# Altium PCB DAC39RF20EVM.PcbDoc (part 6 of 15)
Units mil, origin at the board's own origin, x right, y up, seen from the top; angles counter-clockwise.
Board outline 6200 x 2716.54 mil, 16 copper layers (Top Layer, L2 GND, L3 PWR, L4 GND, L5 PWR, L6 GND, L7 SIG, L8 GND, L9 GND, L10 SIG, L11 GND, L12 PWR, L13 GND, L14 PWR, L15 GND, Bottom Layer), stack 76.97 mil thick; 766 components, 495 nets, 3414 pads, 2373 vias.
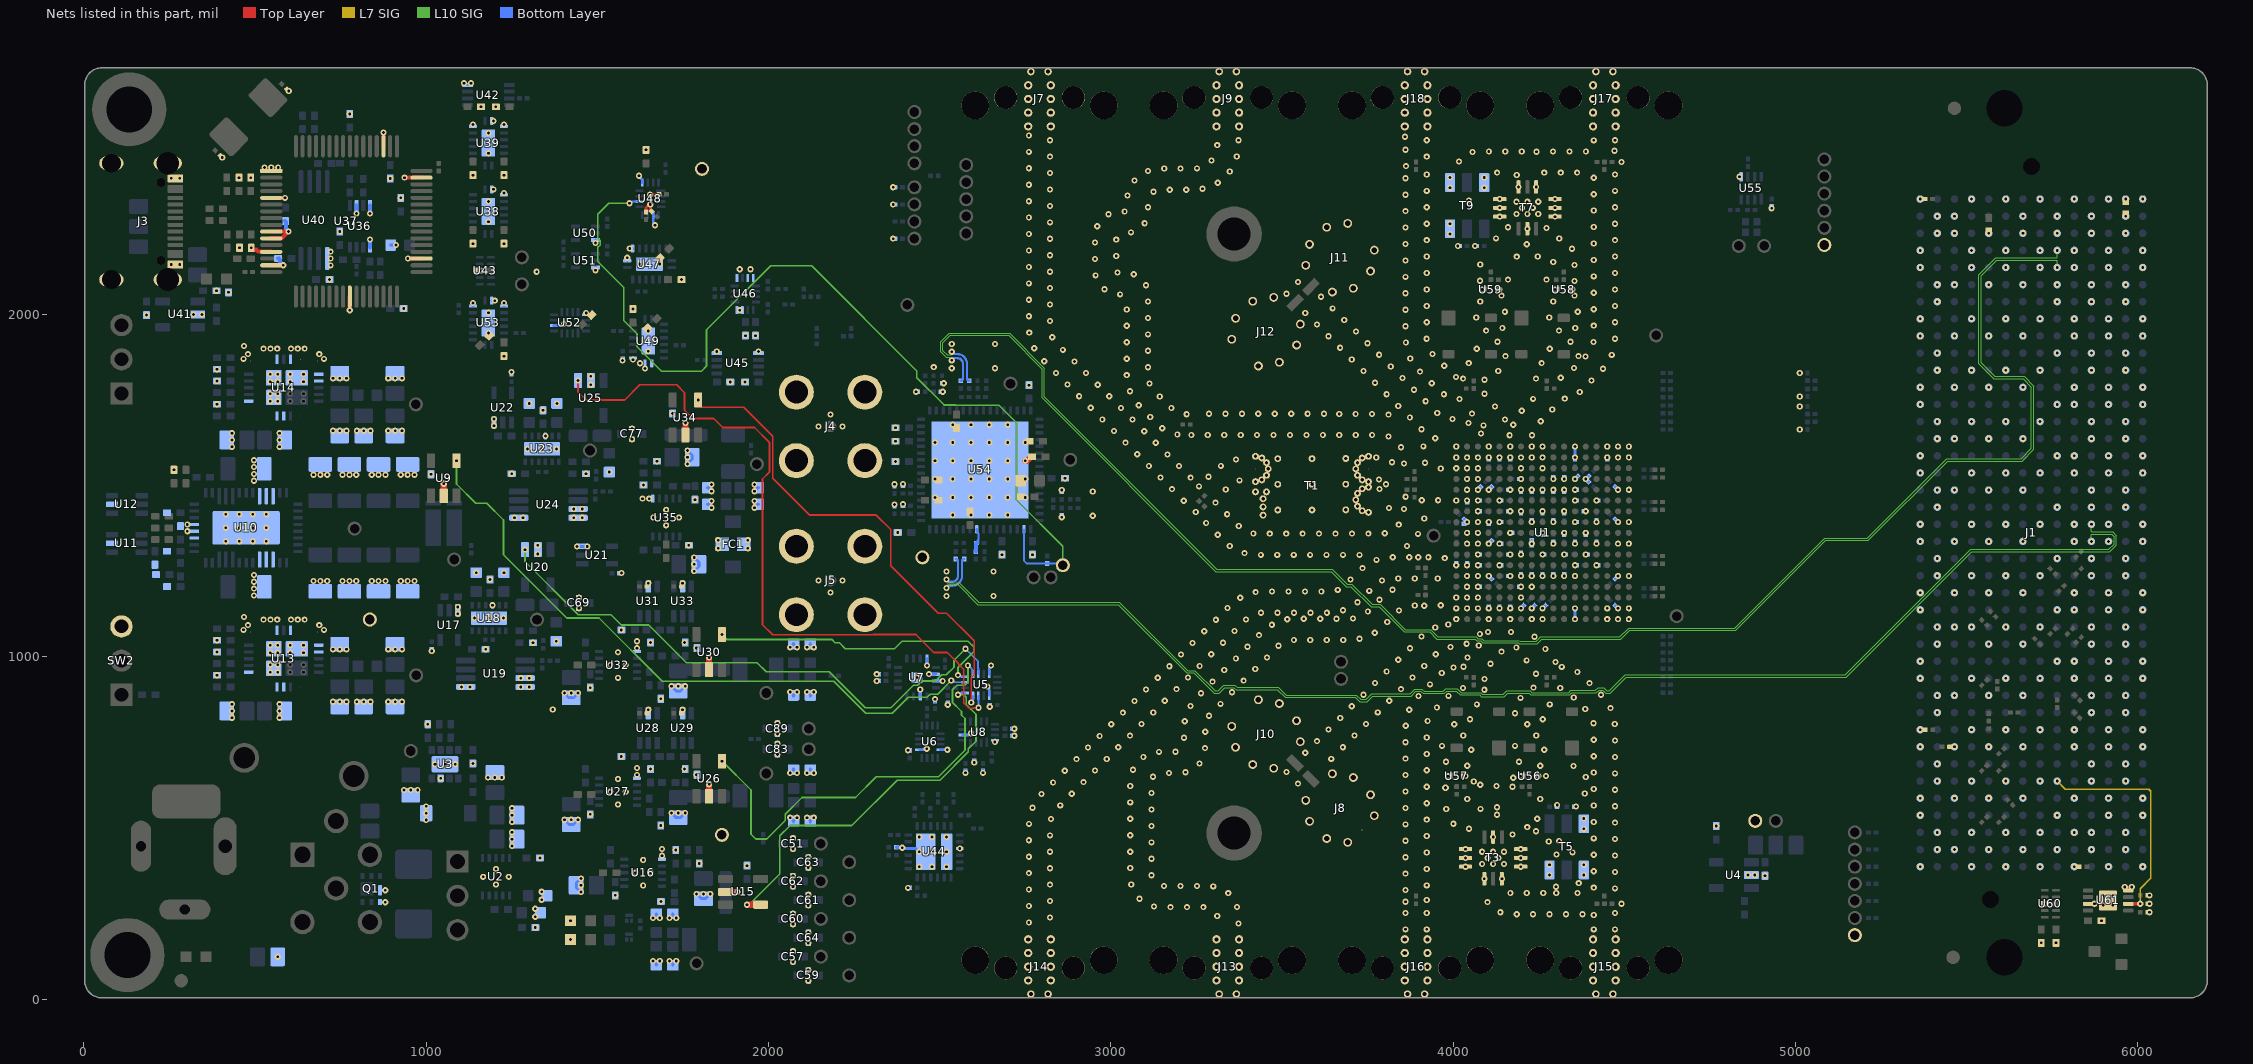
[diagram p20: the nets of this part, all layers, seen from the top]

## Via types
v1: diameter 18, hole 8, Top Layer to Bottom Layer, tented both sides, 2344 vias
v2: diameter 24, hole 12, Top Layer to Bottom Layer, tented both sides, 19 vias
v3: diameter 18, hole 8, Top Layer to Bottom Layer, tented bottom, 9 vias
v4: diameter 20, hole 10, Top Layer to Bottom Layer, tented both sides, 1 vias

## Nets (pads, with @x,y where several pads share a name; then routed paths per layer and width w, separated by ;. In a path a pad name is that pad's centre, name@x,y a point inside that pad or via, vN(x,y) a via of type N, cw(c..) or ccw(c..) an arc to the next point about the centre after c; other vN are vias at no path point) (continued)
GA1_FMC: J1.D35 R196.2 U61.2 | length 662.6
  Top Layer w10: U61.2@5971.65,278.48 v1(6006.65,278.48)
  L7 SIG w5: v1(5764.01,637.07) 5788.05,613.03 6031.97,613.03 6037.59,607.4 6037.59,353.8 6006.65,322.86 v1(6006.65,278.48)
GBTCLK0_FMC_n: C173.1 J1.D5 | length 4914.1
  L10 SIG w3: v1(2535.13,1890.86) 2535.13,1883.59 2533.38,1881.84 2521.81,1881.84 2509.4,1894.25 2509.4,1916.84 2531.07,1938.5 2701.01,1938.5 2798.9,1840.62 2798.9,1756.94 3306.99,1248.85 3643.61,1248.85 3687.39,1205.07 3700.97,1205.07 3759.97,1146.07 3783.69,1146.07 3857.15,1072.61 3931.31,1072.61 3952.24,1051.68 4063.71,1051.68 4068.86,1046.53 4079.9,1046.53 4085.95,1040.48 4189.93,1040.48 4192.39,1038.02 4245.8,1038.02 4258.78,1051 4489.51,1051 4515.38,1076.88 4825.68,1076.88 5088.5,1339.7 5212.86,1339.7 5444.84,1571.69 5661.8,1571.69 5696.01,1605.9 5696.01,1789.97 5667.18,1818.8 5582.28,1818.8 5542.61,1858.47 5542.61,2113.39 5587.78,2158.57 5762.25,2158.57 5764.01,2156.81 v1(5764.01,2137.07)
  Bottom Layer w6.3: v1@2534.74,1890.86 ccw(c2541.36,1890.86) 2541.36,1884.24 2551.25,1884.24 cw(c2551.25,1855.77) 2579.71,1855.77 2579.71,1812.73 ccw(c2586.34,1812.73) C173.1@2586.34,1806.11
GBTCLK0_FMC_p: C172.1 J1.D4 | length 4918.7
  L10 SIG w3: v1(2535.13,1865.81) 2535.13,1873.08 2533.38,1874.84 2518.91,1874.84 2502.4,1891.35 2502.4,1906.43 2502.4,1919.73 2528.17,1945.5 2703.91,1945.5 2805.9,1843.52 2805.9,1759.84 3309.89,1255.85 3646.51,1255.85 3690.29,1212.07 3703.87,1212.07 3762.87,1153.07 3786.59,1153.07 3860.05,1079.61 3934.21,1079.61 3955.14,1058.68 4066.61,1058.68 4072.18,1053.11 4083.22,1053.11 4088.85,1047.48 4192.83,1047.48 4195.29,1045.02 4242.9,1045.02 4255.88,1058 4486.61,1058 4512.48,1083.88 4822.78,1083.88 5085.61,1346.7 5209.96,1346.7 5441.94,1578.69 5658.9,1578.69 5689.01,1608.8 5689.01,1787.07 5664.28,1811.8 5579.38,1811.8 5535.61,1855.57 5535.61,2116.29 5584.88,2165.57 5762.25,2165.57 5764.01,2167.32 v1(5764.01,2187.07)
  Bottom Layer w6.3: v1@2534.74,1865.81 cw(c2541.36,1865.81) 2541.36,1872.44 2551.25,1872.44 cw(c2551.25,1855.77) 2567.91,1855.77 2567.91,1812.73 cw(c2561.29,1812.73) C172.1@2561.29,1806.11
GBTCLK1_FMC_n: C169.1 J1.B21 | length 4002.5
  L10 SIG w3: v1(2520.05,1225.85) 2520.05,1218.58 2521.81,1216.82 2556.88,1216.82 2614.31,1159.39 3025.13,1159.39 3224.63,959.89 3245.64,959.89 3305.22,900.31 3313.2,900.31 3329.82,916.93 3362.38,916.93 3368.53,910.78 3489.01,910.78 3511.54,888.25 3717.14,888.25 3729.53,875.87 3745.76,875.87 3762.01,892.12 3841.61,892.12 3841.67,892.06 3873.97,892.06 3887.79,905.88 3908.74,905.88 3914.66,899.96 3971.17,899.96 3977.67,906.46 4011.71,906.46 4022.69,895.48 4080.07,895.48 4085.26,890.28 4146.22,890.28 4156.54,900.61 4224.49,900.61 4229.62,895.48 4337.03,895.48 4343.3,901.75 4415.19,901.75 4423.03,909.6 4440.18,909.6 4448.89,900.88 4456.26,900.88 4502.9,947.52 5145.47,947.52 5511.8,1313.85 5915.07,1313.85 5930.22,1329 5930.22,1351.18 5922.84,1358.57 5865.77,1358.57 5864.01,1356.81 v1(5864.01,1337.07)
  Bottom Layer w6.3: v1(2520.05,1225.85) ccw(c2526.68,1225.85) 2526.68,1219.22 2536.57,1219.22 ccw(c2536.57,1235.89) 2553.23,1235.89 2553.23,1278.93 ccw(c2546.61,1278.93) C169.1@2546.61,1285.55
GBTCLK1_FMC_p: C168.1 J1.B20 | length 4044.2
  L10 SIG w3: v1(2520.05,1200.8) 2520.05,1208.07 2521.81,1209.82 2553.98,1209.82 2611.41,1152.39 3022.23,1152.39 3221.73,952.89 3242.74,952.89 3302.33,893.31 3316.1,893.31 3332.72,909.93 3359.48,909.93 3365.63,903.78 3486.11,903.78 3508.64,881.25 3714.24,881.25 3726.63,868.87 3748.66,868.87 3764.91,885.12 3838.71,885.12 3838.77,885.06 3876.87,885.06 3890.69,898.88 3905.84,898.88 3911.76,892.96 3974.07,892.96 3980.57,899.46 4008.81,899.46 4019.79,888.48 4077.17,888.48 4082.37,883.28 4149.12,883.28 4159.44,893.61 4221.59,893.61 4226.72,888.48 4339.93,888.48 4346.2,894.75 4418.09,894.75 4425.93,902.6 4437.28,902.6 4445.99,893.88 4459.16,893.88 4505.8,940.52 5148.37,940.52 5514.7,1306.85 5917.97,1306.85 5937.22,1326.1 5937.22,1354.08 5925.74,1365.57 5865.77,1365.57 5864.01,1367.32 v1(5864.01,1387.07)
  Bottom Layer w6.3: v1(2520.05,1200.8) cw(c2526.68,1200.8) 2526.68,1207.42 2536.57,1207.42 ccw(c2536.57,1235.89) 2565.03,1235.89 2565.03,1278.93 cw(c2571.65,1278.93) C168.1@2571.65,1285.55
GND: C2.1 C3.1 C4.1 C5.1 C6.1 C7.1 C8.1 C9.1 C10.1 C11.2 C12.2 C13.2 C14.2 C15.2 C16.2 C17.2 C18.2 C19.1 C20.1 C21.1 C22.1 C23.1 C24.1 C25.1 C26.1 C27.1 C28.1 C29.1 C30.1 C31.1 C32.1 C33.1 C34.1 C35.1 C36.1 C37.1 C38.1 C39.2 C40.1 C41.1 C42.1 C43.1 C44.1 C45.1 C46.1 C47.2 C48.1 C49.1 C50.1 C51.2 C52.1 C53.1 C54.1 C55.1 C56.1 C57.2 C58.1 C59.2 C60.2 C61.2 C62.2 C63.2 C64.2 C65.1 C66.1 C67.1 C69.2 C70.1 C71.1 C72.1 C73.1 C74.1 C75.1 C77.2 C78.1 C79.1 C80.1 C81.1 C82.1 C83.2 C84.1 C85.1 C86.1 C87.1 C88.1 C89.2 C90.1 C91.1 C92.1 C93.1 C94.1 C95.1 C96.1 C97.1 C98.1 C99.1 C100.2 C101.2 C102.2 C103.2 C104.1 C105.1 C106.1 C107.1 C108.1 C109.1 C110.1 C111.1 C112.1 C113.1 C114.1 C115.1 C116.1 C117.1 C118.1 C119.1 C120.1 C121.1 C122.1 C123.1 C124.1 C125.1 C126.1 C127.1 C128.1 C129.1 C130.1 C131.1 C132.1 C133.1 C134.1 C135.1 C136.2 C137.2 C138.2 C139.2 C140.1 C141.2 C142.2 C143.2 C144.2 C145.1 C146.1 C147.2 C148.2 C149.2 C150.2 C151.2 C152.2 C153.2 C154.2 C155.2 C156.2 C157.2 C158.2 C159.2 C161.1 C164.1 C176.1 C177.2 C217.1 C219.1 C226.2 C227.2 C234.2 C235.2 C236.2 C237.2 C238.2 C239.2 C240.2 C241.2 C242.2 C243.2 C244.2 C245.2 C246.2 C247.2 C248.2 C249.2 C250.2 C251.2 C252.2 C253.2 C254.2 C255.2 C256.2 C257.2 C258.2 C259.2 C260.2 C261.2 C262.2 C263.2 C264.2 C265.2 C266.2 C267.2 C268.2 C269.2 C270.2 C271.2 C272.2 C273.2 C274.2 C275.2 C276.2 C277.2 C278.2 C279.2 C280.2 C281.2 C282.2 C283.2 C284.2 C285.2 C286.2 C287.2 C288.2 C289.2 C290.2 C291.2 C292.2 C293.2 C294.2 C295.2 C296.2 C297.2 C298.2 C299.2 C300.2 C301.2 C302.2 C303.2 C304.2 C305.2 C306.2 C307.2 C308.2 C309.2 C310.2 C311.2 C312.2 C313.2 C314.2 C315.1 C316.1 D3.2 D6.2 D7.2 FC1.2 J1.A1 J1.A4 J1.A5 J1.A8 J1.A9 J1.A12 J1.A13 J1.A16 J1.A17 J1.A20 J1.A21 J1.A24 J1.A25 J1.A28 J1.A29 J1.A32 J1.A33 J1.A36 J1.A37 J1.A40 J1.B2 J1.B3 J1.B6 J1.B7 J1.B10 J1.B11 J1.B14 J1.B15 J1.B18 J1.B19 J1.B22 J1.B23 J1.B26 J1.B27 J1.B30 J1.B31 J1.B34 J1.B35 J1.B38 J1.B39 J1.C1 J1.C4 J1.C5 J1.C8 J1.C9 J1.C12 J1.C13 J1.C16 J1.C17 J1.C20 J1.C21 J1.C24 J1.C25 J1.C28 J1.C29 J1.C32 J1.C33 J1.C36 J1.C38 J1.C40 J1.D2 J1.D3 J1.D6 J1.D7 J1.D10 J1.D13 J1.D16 J1.D19 J1.D22 J1.D25 J1.D28 J1.D37 J1.D39 J1.E1 J1.E4 J1.E5 J1.E8 J1.E11 J1.E14 J1.E17 J1.E20 J1.E23 J1.E26 J1.E29 J1.E32 J1.E35 J1.E38 J1.E40 J1.F2 J1.F3 J1.F6 J1.F9 J1.F12 J1.F15 J1.F18 J1.F21 J1.F24 J1.F27 J1.F30 J1.F33 J1.F36 J1.F39 J1.G1 J1.G4 J1.G5 J1.G8 J1.G11 J1.G14 J1.G17 J1.G20 J1.G23 J1.G26 J1.G29 J1.G32 J1.G35 J1.G38 J1.G40 J1.H3 J1.H6 J1.H9 J1.H12 J1.H15 J1.H18 J1.H21 J1.H24 J1.H27 J1.H30 J1.H33 J1.H36 J1.H39 J1.J1 J1.J4 J1.J5 J1.J8 J1.J11 J1.J14 J1.J17 J1.J20 J1.J23 J1.J26 J1.J29 J1.J32 J1.J35 J1.J38 J1.J40 J1.K2 J1.K3 J1.K6 J1.K9 J1.K12 J1.K15 J1.K18 J1.K21 J1.K24 J1.K26 J1.K30 J1.K33 J1.K36 J1.K39 J1.L2 J1.L3 J1.L6 J1.L7 J1.L10 J1.L11 J1.L14 J1.L15 J1.L18 J1.L19 J1.L22 J1.L23 J1.L26 J1.L27 J1.L30 J1.L31 J1.L34 J1.L35 J1.L38 J1.L39 J1.M1 J1.M4 J1.M5 J1.M8 J1.M9 J1.M12 J1.M13 J1.M16 J1.M17 J1.M20 J1.M21 J1.M24 J1.M25 J1.M28 J1.M29 J1.M32 J1.M33 J1.M36 J1.M37 J1.M40 J1.Y1 J1.Y4 J1.Y5 J1.Y8 J1.Y9 J1.Y12 J1.Y13 J1.Y16 J1.Y17 J1.Y20 J1.Y21 J1.Y24 J1.Y25 J1.Y28 J1.Y29 J1.Y32 J1.Y33 J1.Y36 J1.Y37 J1.Y40 J1.Z2 J1.Z3 J1.Z6 J1.Z7 J1.Z10 J1.Z11 J1.Z14 J1.Z15 J1.Z18 J1.Z19 J1.Z22 J1.Z23 J1.Z26 J1.Z27 J1.Z30 J1.Z31 J1.Z34 J1.Z35 J1.Z38 J1.Z39 J3.1 J3.2 J3.3 J3.4 J3.A1 J3.B1 J4.2 J4.3 J4.4 J4.5 J5.2 J5.3 J5.4 J5.5 J7.2 J7.3 J7.4 J8.2 J9.2 J9.3 J9.4 J10.2 J11.2 J12.2 J13.2 J13.3 J13.4 J14.2 J14.3 J14.4 J15.2 J15.3 J15.4 J16.2 J16.3 J16.4 J17.2 J17.3 J17.4 J18.2 J18.3 J18.4 pad.1@942.86,1346.82 pad.1@5001.22,1375.07 PP3.1 PP4.1 PP5.1 PP6.1 PP7.1 PP8.1 PP9.1 Q1.4 Q1.7 R2.1 R3.1 R4.1 R11.1 R13.2 R14.2 R15.2 R25.1 R27.1 R28.1 R30.2 R31.2 R36.1 R37.1 R41.1 R42.1 R48.1 R50.1 R55.1 R56.1 R63.1 R64.1 R73.1 R74.2 R76.1 R81.2 R86.1 R88.1 R94.1 R96.1 R108.1 R110.1 R130.2 R131.2 R142.2 R143.2 R144.2 R148.2 R154.2 R155.2 R156.2 R157.1 R159.1 R160.1 R161.1 R166.1 R167.1 R168.1 R169.1 R170.1 R181.1 R194.1 R195.1 R196.1 R197.1 R198.1 R220.1 R229.1 R230.1 R231.1 R232.1 SW2.2 T1.4 T3.2 T3.4 T3.5 T3.6 T3.7 T3.9 T3.10 T3.11 T3.12 T3.13 T5.3 T5.4 T5.6 T7.2 T7.4 T7.5 T7.6 T7.7 T7.9 T7.10 T7.11 T7.12 T7.13 T9.3 T9.4 T9.6 U1.A1 U1.A2 U1.A3 U1.A6 U1.A9 U1.A10 U1.A12 U1.A14 U1.A17 U1.B1 U1.B2 U1.B3 U1.B6 U1.B9 U1.B10 U1.B11 U1.B12 U1.B13 U1.B14 U1.B15 U1.B16 U1.B17 U1.C11 U1.C15 U1.C16 U1.C17 U1.D10 U1.D11 U1.D15 U1.D16 U1.E1 U1.E2 U1.E6 U1.E7 U1.E8 U1.E9 U1.E10 U1.E11 U1.E12 U1.E14 U1.E15 U1.E16 U1.F4 U1.F6 U1.F13 U1.F15 U1.F16 U1.F17 U1.G5 U1.G7 U1.G9 U1.G11 U1.G12 U1.G15 U1.H1 U1.H2 U1.H4 U1.H6 U1.H8 U1.H10 U1.H13 U1.H14 U1.H15 U1.H16 U1.J5 U1.J7 U1.J9 U1.J12 U1.J15 U1.J16 U1.K1 U1.K2 U1.K4 U1.K6 U1.K8 U1.K10 U1.K13 U1.K14 U1.K15 U1.K16 U1.L5 U1.L7 U1.L9 U1.L11 U1.L12 U1.L15 U1.M4 U1.M6 U1.M13 U1.M15 U1.M16 U1.M17 U1.N1 U1.N2 U1.N6 U1.N7 U1.N8 U1.N9 U1.N10 U1.N11 U1.N12 U1.N14 U1.N15 U1.N16 U1.P5 U1.P6 U1.P7 U1.P8 U1.P11 U1.P15 U1.P16 U1.R9 U1.R11 U1.R15 U1.R16 U1.R17 U1.T1 U1.T2 U1.T3 U1.T6 U1.T9 U1.T10 U1.T11 U1.T12 U1.T13 U1.T14 U1.T15 U1.T16 U1.T17 U1.U1 U1.U2 U1.U3 U1.U6 U1.U9 U1.U10 U1.U12 U1.U14 U1.U17 U2.11 U3.3 U3.9 U4.2 U5.1 U5.12 U6.1 U6.12 U7.2 U7.3 U7.6 U7.16 U7.17 U8.6 U8.16 U9.2 U10.10 U10.11 U10.12 U10.27 U10.28 U10.29 U10.41 U10.42 U10.43 U10.47 U10.48 U10.49 U10.50 U10.51 U11.2 U12.2 U13.1 U13.2 U13.3 U13.5 U13.6 U13.7 U13.8 U13.9 U13.16 U13.17 U13.20 U13.25 U13.26 U13.28 U14.1 U14.2 U14.3 U14.5 U14.6 U14.7 U14.8 U14.9 U14.16 U14.17 U14.20 U14.25 U14.26 U14.28 U15.2 U16.6 U16.11 U17.3 U18.4 U18.13 U19.3 U19.4 U19.5 U20.2 U21.3 U22.3 U23.4 U23.13 U24.3 U24.4 U24.5 U25.2 U26.2 U27.6 U27.11 U28.2 U29.2 U30.2 U31.2 U32.6 U32.11 U33.2 U34.2 U35.6 U35.11 U36.2 U36.4 U36.5 U37.1 U37.5 U37.10 U37.11 U37.13 U37.15 U37.25 U37.35 U37.47 U37.51 U38.9 U38.10 U38.17 U39.7 U39.9 U39.10 U39.17 U40.5 U41.2 U42.4 U43.3@1156.57,2127.4 U44.9 U44.22 U44.25 U44.26 U45.4 U45.5 U46.5 U46.7 U46.8 U46.15 U46.16 U47.9 U47.10 U47.17 U48.6 U48.13 U49.8 U49.9 U49.10 U49.17 U50.3 U51.3 U52.6 U52.13 U53.7 U53.9 U53.10 U53.17 U54.65 U55.5 U56.3 U57.3 U58.3 U59.3 U60.3@5727.59,278.48 U61.4 U61.7 U61.9 | length 3442.8
  Top Layer w5: C101.2@1645.41,835.18 1645.41,841.64 cw(c1648.95,841.64) v1(1648.95,845.18) ; C102.2@1645.41,1205.18 1645.41,1211.64 cw(c1648.96,1211.64) v1(1648.96,1215.18) ; C100.2@1745.41,835.18 1745.41,841.64 cw(c1748.95,841.64) v1(1748.95,845.18) ; C103.2@1745.41,1205.18 1745.41,1211.64 cw(c1748.95,1211.64) v1(1748.95,1215.18) ; U54.65@2486.29,1465.51 2494.56,1457.25 C154.2@2496.14,1457.25 ; U54.65@2486.29,1519.06 2489.05,1516.3 C155.2@2496.14,1516.3 ; U54.65@2537.87,1677.72 2539.26,1679.11 2540.02,1679.11 2549.29,1669.85 C157.2@2549.29,1667.88 ; C152.2@2588.66,1423.78 2591.41,1421.03 U54.65@2591.41,1413.94 ; C176.1@2736.59,1514.36 2741.28,1519.06 U54.65@2750.07,1519.06 ; C177.2@2738,1467.83 2749.81,1467.83 2750.07,1467.57 U54.65@2750.07,1465.51 ; U54.65@2750.07,1626.14 2750.07,1629.33 2750.23,1629.49 R169.1@2762.04,1629.49
  Top Layer w8: v1(1467.36,2003.97) 1470.07,2003.97 1475.74,1998.3 C145.1@1483.39,1998.3 ; R144.2@1642.36,2299.31 1642.36,2311.95 1646.23,2315.82 1646.92,2315.82 1651.92,2320.82 v1(1654.63,2320.82) 1654.63,2306.11 1653.26,2306.11 R143.2@1658.27,2301.1 ; U49.17@1647.87,1947.16 1647.87,1950.49 U49.17@1649.11,1951.73 ; v1(1653.73,2349.56) 1654.8,2350.62 R142.2@1679.68,2350.62 ; v1@1668.11,2260.07 v1(1668.11,2260.51) ; U47.17@1681.88,2147.1 1681,2147.99 1681,2163.15 C142.2@1682.39,2164.54
  Top Layer w10: v1(5364.01,787.07) R231.1@5378.68,787.07 ; v1(5364.01,2337.07) R230.1@5377.99,2337.07 ; R232.1@5450.04,737.07 v1(5464.01,737.07) ; v1(5564.01,2237.07) R220.1@5564.01,2242.38 ; v1(5814.01,387.07) R198.1@5828.68,387.07 ; U61.7@5854.4,278.48 5854.6,278.68 5872.96,278.68 v1(5873.16,278.89) ; v1(5961.65,327.85) U61.4@5971.65,317.85 v1(5981.65,327.85) ; v1(5964.01,2287.07) R229.1@5964.01,2292.38 ; R195.1@6028.7,253.79 v1(6033.7,253.79) ; R196.1@6028.7,278.48 v1(6033.7,278.48) ; R197.1@6028.7,303.16 v1(6033.7,303.16)
  Top Layer w12: C129.1@399.3,2463.36 v1(404.3,2458.36) ; v1(488.97,2194.67) 488.97,2192.71 492.81,2188.86 503.92,2188.86 509.41,2183.37 547.25,2183.37 U37.13@547.59,2183.03 ; U37.15@547.59,2143.66 v1(582.59,2143.66) ; U37.11@547.59,2222.4 577.91,2222.4 v1(597.59,2242.08) U37.10@547.59,2242.08 ; U37.5@547.59,2340.51 v1(587.59,2340.51) ; C130.1@593.44,2657.5 v1(598.44,2652.5) ; v1(776.93,2012.12) U37.25@776.93,2052.12 ; U37.51@875.35,2491.1 v1(875.35,2531.1) ; v1(936.57,2399.56) U37.47@986.57,2399.56 ; v1(946.57,2163.34) U37.35@986.57,2163.34
  Top Layer w18: U9.2@1051.42,1470.25 v1(1051.42,1505.25) ; U34.2@1757.19,1647.65 v1(1757.19,1682.65) ; U26.2@1826.57,592.47 v1(1826.57,627.47) ; U30.2@1826.57,962.47 v1(1826.57,997.47) ; U15.2@1874.64,313.21 v1(1909.64,313.21) ; U54.65@2750.07,1572.6 2755.38,1572.6 2767.31,1584.53 R170.1@2769.28,1584.53
  Bottom Layer w5: v1(1016.14,1017.1) C65.1@1016.14,1022.1 ; U42.4@1110.82,2670.47 v1(1110.82,2675.47) 1115.82,2670.47 U42.4@1120.82,2670.47 1125.82,2670.47 v1(1130.82,2675.47) U42.4@1130.82,2670.47 ; U39.7@1136.57,2549.56 v1(1136.57,2554.56) ; U38.9@1191.69,2365.31 v1(1196.69,2365.31) ; U39.9@1191.69,2565.31 v1(1196.69,2565.31) ; U38.10@1227.12,2349.56 v1(1227.12,2354.56) ; U39.10@1227.12,2549.56 v1(1227.12,2554.56) ; U52.13@1467.36,1999.25 v1(1467.36,2003.97) ; U46.16@1908.03,2012.46 v1(1915.91,2012.46) U46.15@1923.78,2012.46 ; R161.1@2367.91,1439.92 v1(2367.91,1444.92) ; R157.1@2367.91,1498.98 v1(2367.91,1503.98) ; C164.1@2392.91,1440.92 v1(2392.91,1445.92) ; C161.1@2392.91,1499.98 v1(2392.91,1504.98) ; v1(2430.62,1774.06) R166.1@2435.62,1774.06 ; R167.1@2503.9,1774.06 v1(2508.9,1774.06) ; R168.1@2506.85,1799.06 v1(2511.85,1799.06) ; v1(2856.41,1407.83) R160.1@2856.41,1412.83 ; R159.1@2856.41,1481.98 v1(2856.41,1486.98) ; C219.1@4031.07,1388.46 4031.86,1388.46 4038.16,1394.76 4039.22,1394.76 v1(4040.52,1393.46) ; v1(4072.02,1204.49) C305.2@4076.74,1204.49 ; v1(4072.02,1267.48) C286.2@4076.74,1267.48 ; v1(4072.02,1298.98) C285.2@4076.74,1298.98 ; v1(4103.52,1141.5) C300.2@4103.52,1146.22 ; C282.2@4103.52,1388.75 v1(4103.52,1393.46) ; C294.2@4103.52,1577.7 C294.2@4103.52,1582.44 ; v1(4135.01,1141.5) C301.2@4135.01,1146.22 ; v1(4135.01,1267.48) C313.2@4139.74,1267.48 ; v1(4135.01,1330.47) C311.2@4139.74,1330.47 ; v1(4135.01,1393.46) C309.2@4139.74,1393.46 ; v1(4135.01,1456.46) C307.2@4139.74,1456.46 ; C295.2@4135.01,1577.7 C295.2@4135.01,1582.44 ; C314.2@4161.78,1235.98 v1(4166.51,1235.98) ; C312.2@4161.78,1298.98 v1(4166.51,1298.98) ; C308.2@4161.78,1424.96 v1(4166.51,1424.96) ; C306.2@4161.78,1487.95 v1(4166.51,1487.95) ; v1(4166.51,1141.5) C302.2@4166.51,1146.22 ; v1(4166.51,1361.97) C310.2@4171.23,1361.97 ; C296.2@4166.51,1577.7 C296.2@4166.51,1582.44 ; C303.2@4193.28,1204.49 v1(4198,1204.49) ; C297.2@4193.26,1519.45 v1(4198,1519.45) ; v1@4198,1231.27 v1(4198,1235.98) ; v1(4198,1298.98) C276.2@4198,1303.7 ; C279.2@4198,1420.24 v1(4198,1424.96) ; C278.2@4198,1483.23 v1(4198,1487.95) ; v1(4229.5,1235.98) C268.2@4229.5,1240.71 ; C264.2@4229.5,1325.75 v1(4229.5,1330.47) ; v1(4229.5,1393.46) C253.2@4229.5,1398.19 ; C243.2@4229.5,1483.23 v1(4229.5,1487.95) ; v1(4261,1235.98) C269.2@4261,1240.71 ; v1(4261,1298.98) C265.2@4265.72,1298.98 ; C258.2@4261,1357.24 v1(4261,1361.97) ; C254.2@4261,1420.24 v1(4261,1424.96) ; C244.2@4261,1483.23 v1(4261,1487.95) ; v1(4292.49,1235.98) C270.2@4292.49,1240.71 ; v1(4292.49,1330.47) C259.2@4292.49,1335.2 ; v1(4292.49,1393.46) C255.2@4292.49,1398.19 ; C245.2@4292.49,1483.23 v1(4292.49,1487.95) ; v1(4292.49,1519.45) C242.2@4292.49,1524.17 ; v1(4323.99,1235.98) C271.2@4323.99,1240.71 ; v1(4323.99,1298.98) C266.2@4328.71,1298.98 ; C260.2@4323.99,1357.24 v1(4323.99,1361.97) ; C256.2@4323.99,1420.24 v1(4323.99,1424.96) ; C246.2@4323.99,1483.23 v1(4323.99,1487.95) ; v1(4323.99,1519.45) C241.2@4323.99,1524.17 ; v1(4355.48,1267.48) C272.2@4360.21,1267.48 ; v1(4355.48,1330.47) C261.2@4355.48,1335.2 ; v1(4355.48,1393.46) C257.2@4360.21,1393.46 ; v1(4355.48,1456.46) C248.2@4360.21,1456.46 ; v1(4355.48,1487.95) C247.2@4360.21,1487.95 ; C249.2@4382.26,1424.96 v1(4386.98,1424.96) ; v1(4386.98,1298.98) C267.2@4391.71,1298.98 ; C262.2@4386.98,1357.24 v1(4386.98,1361.97) ; v1(4418.48,1267.48) R181.1@4423.2,1267.48 ; v1(4418.48,1330.47) C263.2@4418.48,1335.2 ; v1(4418.48,1393.46) C252.2@4418.48,1398.19 ; v1(4418.48,1456.46) C250.2@4423.2,1456.46 ; C237.2@4449.97,1577.72 C237.2@4449.97,1582.44
  Bottom Layer w8: C118.1@896.45,2202.71 v1(912.2,2202.71) ; U53.7@1136.57,2024.56 v1(1136.57,2033.22) ; U53.9@1191.69,2040.31 v1(1200.35,2040.31) ; U53.10@1227.12,2024.56 v1(1227.12,2033.22) ; U52.6@1372.87,1967.47 1394.35,1967.47 1399.35,1972.47 v1(1402.87,1972.47) ; v1(1403.79,524.19) 1417.79,510.19 C81.1@1423.79,510.19 ; v1(1403.79,894.19) 1417.79,880.19 C92.1@1423.79,880.19 ; v1(1423.79,524.19) C81.1@1423.79,510.19 ; v1(1423.79,894.19) C92.1@1423.79,880.19 ; v1(1440.82,1322.51) U21.3@1455.82,1322.51 v1(1470.82,1322.51) ; v1(1443.79,524.19) 1429.79,510.19 C81.1@1423.79,510.19 ; v1(1443.79,894.19) 1429.79,880.19 C92.1@1423.79,880.19 ; v1(1452.1,312.69) 1438.1,326.69 C49.1@1438.1,332.69 ; v1(1452.1,332.69) C49.1@1438.1,332.69 ; v1(1452.1,352.69) 1438.1,338.69 C49.1@1438.1,332.69 ; v1(1494.29,2128.91) U51.3@1494.29,2137.58 ; v1(1494.29,2208.91) U50.3@1494.29,2217.58 ; v1(1573.83,1865.62) R148.2@1573.83,1870.62 ; U47.9@1587.39,2156.95 v1(1587.39,2165.61) ; v1(1594.48,2192.38) U47.10@1603.14,2192.38 ; v1(1603.83,1867.99) U49.10@1603.83,1872.99 ; v1(1621.61,2404.99) 1621.61,2402.87 1631.61,2392.87 U48.13@1631.61,2384.99 ; v1(1662.37,111.63) C56.1@1672.37,101.63 ; v1(1662.37,237.23) C54.1@1672.37,247.23 ; U48.6@1663.11,2290.51 1663.11,2268.21 1668.11,2263.21 v1(1668.11,2260.51) ; C56.1@1672.37,99.31 C56.1@1672.37,101.63 ; C54.1@1672.37,249.55 C54.1@1672.37,247.23 ; v1(1682.37,111.63) C56.1@1672.37,101.63 ; v1(1682.37,237.23) C54.1@1672.37,247.23 ; v1(1710.58,111.31) C53.1@1720.58,101.31 ; v1(1710.58,236.91) C55.1@1720.58,246.91 ; v1(1716.52,543.87) 1730.52,529.87 C84.1@1736.52,529.87 ; v1(1716.52,913.87) 1730.52,899.87 C94.1@1736.52,899.87 ; C53.1@1720.58,98.99 C53.1@1720.58,101.31 ; C55.1@1720.58,249.23 C55.1@1720.58,246.91 ; v1(1730.58,111.31) C53.1@1720.58,101.31 ; v1(1730.58,236.91) C55.1@1720.58,246.91 ; v1(1736.52,543.87) C84.1@1736.52,529.87 ; v1(1736.52,913.87) C94.1@1736.52,899.87 ; v1(1756.52,543.87) 1742.52,529.87 C84.1@1736.52,529.87 ; v1(1756.52,913.87) 1742.52,899.87 C94.1@1736.52,899.87 ; v1(1763.07,1562.9) 1777.07,1576.9 C107.1@1777.07,1582.9 ; v1(1763.07,1582.9) C107.1@1777.07,1582.9 ; v1(1763.07,1602.9) 1777.07,1588.9 C107.1@1777.07,1582.9 ; v1(1782.76,1250.17) 1796.76,1264.17 C105.1@1796.76,1270.17 ; v1(1782.76,1270.17) C105.1@1796.76,1270.17 ; v1(1782.76,1290.17) 1796.76,1276.17 C105.1@1796.76,1270.17 ; v1(1789.89,307.32) 1803.89,293.32 C52.1@1809.89,293.32 ; v1(1809.89,307.32) C52.1@1809.89,293.32 ; C109.1@1820.85,1445.38 C109.1@1823.17,1445.38 ; C110.1@1821.17,1493.6 C110.1@1823.49,1493.6 ; v1(1829.89,307.32) 1815.89,293.32 C52.1@1809.89,293.32 ; v1(1833.17,1435.38) C109.1@1823.17,1445.38 ; v1(1833.17,1455.38) C109.1@1823.17,1445.38 ; v1(1833.49,1483.6) C110.1@1823.49,1493.6 ; v1(1833.49,1503.6) C110.1@1823.49,1493.6 ; U45.4@1848.98,1886.77 v1(1848.98,1891.77) ; v1(1958.77,1435.38) C111.1@1968.77,1445.38 ; v1(1958.77,1455.38) C111.1@1968.77,1445.38 ; v1(1959.08,1483.6) C108.1@1969.08,1493.6 ; v1(1959.08,1503.6) C108.1@1969.08,1493.6 ; U45.5@1971.03,1886.77 v1(1971.03,1891.77) ; C111.1@1971.09,1445.38 C111.1@1968.77,1445.38 ; C108.1@1971.4,1493.6 C108.1@1969.08,1493.6 ; v1(2063.1,530.11) C85.1@2073.1,520.11 ; v1(2063.1,660.34) C88.1@2073.1,670.34 ; v1(2063.1,897.35) C95.1@2073.1,887.35 ; v1(2063.1,1027.59) C98.1@2073.1,1037.59 ; C85.1@2073.1,517.79 C85.1@2073.1,520.11 ; C88.1@2073.1,672.66 C88.1@2073.1,670.34 ; C95.1@2073.1,885.03 C95.1@2073.1,887.35 ; C98.1@2073.1,1039.91 C98.1@2073.1,1037.59 ; v1(2083.1,530.11) C85.1@2073.1,520.11 ; v1(2083.1,660.34) C88.1@2073.1,670.34 ; v1(2083.1,897.35) C95.1@2073.1,887.35 ; v1(2083.1,1027.59) C98.1@2073.1,1037.59 ; v1(2112.1,530.11) C87.1@2122.1,520.11 ; v1(2112.1,660.34) C86.1@2122.1,670.34 ; v1(2112.1,897.35) C97.1@2122.1,887.35 ; v1(2112.1,1027.59) C96.1@2122.1,1037.59 ; C87.1@2122.1,517.79 C87.1@2122.1,520.11 ; C86.1@2122.1,672.66 C86.1@2122.1,670.34 ; C97.1@2122.1,885.03 C97.1@2122.1,887.35 ; C96.1@2122.1,1039.91 C96.1@2122.1,1037.59 ; v1(2132.1,530.11) C87.1@2122.1,520.11 ; v1(2132.1,660.34) C86.1@2122.1,670.34 ; v1(2132.1,897.35) C97.1@2122.1,887.35 ; v1(2132.1,1027.59) C96.1@2122.1,1037.59 ; v1(2364.08,2221.38) R155.2@2369.08,2221.38 ; v1(2364.08,2321.38) R156.2@2369.08,2321.38 ; v1(2364.08,2371.38) R154.2@2369.08,2371.38 ; U6.1@2441.38,728.38 2456.68,728.38 2459.68,731.38 v1(2462.38,731.38) ; U6.12@2502.41,728.38 v1(2522.41,728.38) ; U8.6@2566.59,771.72 2583.89,771.72 2588.89,776.72 v1(2591.59,776.72) ; v1(2639.54,913.23) 2639.54,910.53 2644.54,905.53 U5.1@2644.54,888.23 ; U5.12@2644.54,949.26 2644.54,966.55 2649.54,971.55 v1(2649.54,974.26) ; v1(4013.48,2200.1) C234.2@4018.48,2200.1 ; C288.2@4032.57,1401.42 4039.22,1394.76 v1(4040.52,1393.46) ; v1(4063.48,2200.1) C235.2@4068.48,2200.1 ; v1(4072.02,1487.95) C299.2@4079.97,1495.91 ; v1(4103.52,1235.98) C304.2@4111.47,1228.03 ; v1(4103.52,1330.47) C283.2@4111.47,1338.43 ; v1(4103.52,1487.95) C298.2@4111.47,1495.91 ; v1(4198,1141.5) C280.2@4205.96,1149.45 ; v1(4229.5,1141.5) C281.2@4237.45,1149.45 ; v1(4229.5,1330.47) C293.2@4229.5,1339.92 ; v1(4261,1141.5) C273.2@4268.95,1149.45 ; C226.2@4303.53,562.45 v1(4303.53,567.45) ; C227.2@4353.53,562.45 v1(4358.53,562.45) ; v1(4355.48,1110) v1(4355.48,1141.5) ; v1(4355.48,1519.45) C239.2@4363.44,1527.4 ; C240.2@4355.48,1577.72 v1(4355.48,1582.44) v1(4355.48,1613.94) ; C284.2@4394.93,1511.5 v1(4386.98,1519.45) C238.2@4394.93,1527.4 ; C275.2@4473.52,1149.45 v1(4481.47,1141.5) ; C274.2@4473.52,1228.03 v1(4481.47,1235.98) ; C251.2@4473.52,1401.42 v1(4481.47,1393.46) ; C236.2@4473.52,1495.91 v1(4481.47,1487.95) ; v1(4836.06,2402.07) U55.5@4841.06,2402.07 ; v1(4930.11,2310.06) C217.1@4930.11,2315.06
  Bottom Layer w9: R130.2@2373.34,443.59 2389.34,443.59 v1(2390.51,442.42) 2392.23,440.69 2396.6,440.69 2397.02,440.27 U44.22@2408.34,440.27 2430.49,440.27 U44.25@2440.33,430.43 ; U7.6@2443.35,884.3 v1(2443.35,904.3) ; v1(2463.04,974.53) U7.16@2463.04,994.53 ; v1(2468.63,949.26) U7.2@2488.63,949.26 ; U7.3@2488.63,929.57 v1(2508.63,929.57)
  Bottom Layer w12: C124.1@567.84,2163.34 569.81,2163.34 573.65,2159.5 573.65,2153.69 582.59,2144.74 v1(582.59,2143.66) ; R110.1@587.59,2272.41 590.4,2269.61 590.4,2250.9 597.59,2243.7 v1(597.59,2242.08) v1@589.59,2242.08 ; v1(796.61,2295.07) U36.2@796.61,2318.07 ; U36.5@835.98,2196.02 v1(835.98,2219.02) ; v1(835.98,2295.07) U36.4@835.98,2318.07 ; v1(2316.34,929.57) C14.2@2321.34,929.57 ; v1(2316.34,949.26) C13.2@2321.34,949.26 ; v1(2407.29,726.81) C18.2@2412.29,726.81 ; v1(2407.38,325.13) R131.2@2412.38,325.13 ; C12.2@2486.04,871.34 v1(2486.04,876.34) ; v1(2523.63,859.84) C11.2@2523.63,864.84 ; v1(2575.21,661.05) R15.2@2575.21,666.05 ; v1(2600.96,691.05) R14.2@2600.96,696.05 ; v1(2626.71,661.05) R13.2@2626.71,666.05 ; v1(2646.11,854.24) C15.2@2646.11,859.24 ; v1(2661.08,750.97) U8.16@2661.08,755.97 ; C17.2@2713.13,769.22 v1(2718.13,769.22) ; C16.2@2713.13,789.97 v1(2718.13,789.97)
  other v1: 2116.36,53.62 2116.35,85.12 2071.36,108.62 566.32,123.65 2071.35,140.12 2116.36,163.62 5717.59,164.43 5760.47,164.43 1421.69,174.11 2116.35,195.12 3860.49,203.88 3922.53,203.88 4410.49,203.88 4472.53,203.88 1318.9,209.42 2071.36,218.62 3372.53,221.32 2760.49,224.05 1421.69,229.11 5893.77,228.79 2822.53,238.43 1318.5,240.47 3310.49,242.61 4410.49,245.88 4185.29,247.78 4233.29,247.78 4281.29,247.78 4329.29,247.78 4377.29,247.78 2071.35,250.12 3860.49,251.88 3922.53,251.88 4472.53,251.88 4137.65,253.6 1318.5,263.94 3174.19,268.68 3222.19,268.68 3270.19,268.68 3368.74,269.17 3126.24,270.98 2760.49,272.05 2116.36,273.62 5727.59,278.48 4491.56,278.8 880.42,283.22 4099.93,283.3 3860.72,284.55 1685.92,285.25 2822.53,286.43 1337.27,290.47 3922.53,289.88 3083.76,293.31 1552.58,303.17 2116.35,305.12 3342.9,309.63 4166.83,309.82 4214.83,309.82 4262.83,309.82 4300.83,309.82 4362.83,309.82 1337.27,313.94 880.42,318.22 3860.72,318.55 2760.49,320.05 4472.53,323.59 4410.49,325.71 2071.36,328.62 4300.47,328.4 3299.2,329.49 3155.22,330.72 3203.22,330.72 3251.22,330.72 3922.76,332.39 2822.53,334.43 3059.74,334.87 4366.79,338.85 4090.92,351.54 4142.1,351.54 2071.35,360.12 4910.77,360.52 3118.8,361.99 4281.48,362.41 4381.48,362.41 4860.77,362.49 4880.77,362.49 3860.72,366.55 2760.49,368.05 4472.53,371.59 4410.49,373.71 3922.76,380.39 2822.53,382.43 2116.36,383.62 3056.77,382.78 4035.8,386.97 4197.22,386.97 5364.01,387.07 5514.01,387.07 5614.01,387.07 5714.01,387.07 5914.01,387.07 6014.01,387.07 1937,389.98 4281.48,392.41 4381.48,392.41 4084.51,394.56 4116.51,394.56 4148.51,394.56 1797.89,396.08 3118.8,409.99 1332.55,412.44 4035.8,412.56 4100.51,412.56 4132.51,412.56 4197.22,412.56 3860.72,414.55 2116.35,415.12 2760.49,416.05 1688.89,418.68 4472.53,419.59 4301.5,422.62 4410.49,421.71 3922.76,428.39 4348.11,428.76 2822.53,430.43 4084.51,430.56 4116.51,430.56 4148.51,430.56 3056.77,430.78 1728.89,435.45 5414.01,437.07 5464.01,437.07 5564.01,437.07 5664.01,437.07 5764.01,437.07 5864.01,437.07 5964.01,437.07 1688.89,438.68 2071.36,438.62 4035.8,438.15 4197.22,438.15 2558.93,440.27 1250.68,447.44 3118.8,457.99 4279.2,460.17 3860.72,462.55 4309.31,462.38 2760.49,464.05 1250.68,467.44 4472.53,467.59 2071.35,470.12 4410.49,469.71 4116.51,473.58 3922.76,476.39 2822.53,478.43 3056.77,478.78 4173.12,481.06 1250.68,487.44 5414.01,487.07 5514.01,487.07 5614.01,487.07 5714.01,487.07 5814.01,487.07 5864.01,487.07 5964.01,487.07 4241.81,490.26 4381.48,497.45 4046.12,497.75 4216.09,502.45 3118.8,505.99 4768.4,505.76 1685.52,507.43 3860.72,510.55 2760.9,512.05 4000.38,512.31 4472.53,515.59 1250.68,517.44 4410.49,517.71 999.9,523.16 3922.76,524.39 2825,526.36 3056.77,526.78 4245.25,527.03 4381.48,527.45 1250.68,537.44 5364.01,537.07 5764.01,537.07 5914.01,537.07 6014.01,537.07 4127.52,538.82 1479.21,539.71 999.9,543.16 3118.8,553.99 3979.41,555.49 4079.59,555.9 1250.68,557.44 3860.72,558.55 2771.33,558.9 4127.5,560.69 999.9,563.16 4472.53,563.59 2852.01,566.04 4410.49,565.71 3922.76,572.39 3056.77,574.78 4041.02,584.48 4254.03,584.48 5364.01,587.07 5464.01,587.07 5564.01,587.07 5664.01,587.07 5814.01,587.07 5914.01,587.07 6014.01,587.07 2797.64,599.05 2885.95,599.98 4384.22,600.82 3118.8,601.99 3860.72,606.55 935.09,610.74 955.09,610.74 975.09,610.74 4472.53,611.59 4410.49,613.71 3922.76,620.39 4172.97,620.63 3056.77,622.78 4126.63,622.73 4078.76,626.32 3546.69,629.43 2831.4,633.17 2919.89,633.92 4060.05,635.63 5414.01,637.07 5514.01,637.07 5614.01,637.07 5714.01,637.07 5864.01,637.07 5964.01,637.07 1042.3,644.95 1180.72,647.22 1200.72,647.22 1220.72,647.22 4175.21,646.79 4386.96,648.74 3123.12,649.8 3984.45,651.34 4035.55,651.34 4197.46,651.34 4248.57,651.34 4270.96,651.65 3860.72,654.55 1615.52,655.23 1789.17,655.46 4472.53,659.59 3169.86,660.73 4410.49,661.71 3217.82,662.74 3512.75,663.37 2865.34,667.11 2953.84,667.87 3922.76,668.39 3064.33,670.18 1655.52,672 1754.89,672 1615.52,675.23 4351.27,680.84 4041.02,681.8 4254.03,681.8 5414.01,687.07 5864.01,687.07 5964.01,687.07 1136.48,688.26 3258.54,688.14 3978.98,693.26 4192,693.26 2899.28,701.05 2987.78,701.81 3643.61,701.92 3860.72,702.55 3094.92,707.17 4472.53,707.59 1570.18,708.57 4410.49,709.71 2026.02,714.29 3922.76,716.39 3567.94,719.66 3140.45,722.35 3188.45,722.77 4052.69,728.36 4265.71,728.36 3275.24,733.14 2933.23,734.99 3021.72,735.75 3677.55,735.86 5364.01,737.07 5564.01,737.07 5664.01,737.07 5814.01,737.07 5914.01,737.07 6014.01,737.07 3967.31,739.82 4180.33,739.82 2026.02,745.8 3860.72,750.55 3601.88,753.61 4472.53,755.59 4410.49,757.71 3213.47,763.73 3922.76,764.39 2967.17,768.93 3055.66,769.69 3711.5,769.8 4029.28,770.26 4242.29,770.26 2026.02,774.29 3275.51,781.14 3635.82,787.55 5514.01,787.07 5614.01,787.07 5714.01,787.07 5814.01,787.07 5914.01,787.07 6014.01,787.07 3861.18,798.55 1004.7,803 3001.11,802.87 3089.6,803.63 4002.96,802.82 4215.97,802.82 4471.68,803.58 3745.44,803.74 2026.02,805.8 4409.67,805.7 3215.62,811.69 3925.22,812.33 4048.63,817.58 4261.65,817.58 3669.76,821.49 432.77,821.74 571.88,821.74 3286.76,827.81 4180.33,834.97 3035.05,836.81 3123.54,837.57 3779.38,837.68 5414.01,837.07 5864.01,837.07 5964.01,837.07 432.77,841.74 571.88,841.74 3871.75,845.37 1369.67,845.72 4385.74,847.31 4459.57,850.03 3952.22,852.02 3703.7,855.43 3232.55,856.6 4069.04,861.03 4282.06,861.03 432.77,861.74 571.88,861.74 3319.95,862.49 727.63,868.67 747.63,868.67 767.63,868.67 797.63,868.67 817.63,868.67 837.63,868.67 889.36,868.67 909.36,868.67 929.36,868.67 3068.99,870.75 3157.48,871.51 3813.32,871.62 1685.52,877.43 4196.65,880.11 4351.8,881.25 3898.26,885.38 3986.16,885.96 5414.01,887.07 5464.01,887.07 5564.01,887.07 5664.01,887.07 5864.01,887.07 5964.01,887.07 3737.64,889.37 4431.69,889.1 3263.24,893.51 3353.89,896.43 4090.86,903.78 3102.93,904.7 3191.42,905.45 3847.26,905.56 4028.28,908.98 4312.61,908.98 1479.21,909.71 4234.24,909.96 1103.06,912.11 1128.06,912.11 1276.29,912.11 1301.29,912.11 3932,919.53 3771.59,923.31 4397.75,923.04 3297.18,927.45 3387.83,930.37 4091.63,934.8 5364.01,937.07 5514.01,937.07 5614.01,937.07 5714.01,937.07 5814.01,937.07 5914.01,937.07 6014.01,937.07 1276.29,937.7 1301.29,937.7 3136.87,938.64 3225.36,939.39 3881.2,939.51 389.38,946.11 4242,950.29 3966.69,952.71 4362.6,955.73 3805.53,957.25 3331.12,961.39 3421.77,964.31 4000.44,968.68 4316.97,970.64 4029.92,970.87 3170.81,972.58 3259.31,973.34 3915.14,973.45 4108.68,979.67 4298.73,984.8 5364.01,987.07 5764.01,987.07 5814.01,987.07 5914.01,987.07 6014.01,987.07 4214.42,989.58 3839.47,991.19 3365.06,995.33 3455.72,998.25 4041.41,998.08 3204.76,1006.52 3293.25,1007.28 3949.08,1007.39 389.38,1014.11 4141.1,1015.07 727.63,1021.74 747.63,1021.74 767.63,1021.74 889.36,1021.74 909.36,1021.74 929.36,1021.74 1173.86,1021.81 4269.14,1022.6 1615.52,1025.23 1789.17,1025.46 3873.41,1025.13 4184.33,1026.98 3399,1029.27 3992.01,1028.86 3489.7,1032.15 4074.31,1033.03 5414.01,1037.07 5564.01,1037.07 5664.01,1037.07 5864.01,1037.07 5964.01,1037.07 4039.1,1038.18 3238.7,1040.46 1312.28,1040.81 3327.19,1041.22 1655.52,1042 1754.89,1042 1380.28,1045.5 1615.52,1045.23 389.38,1048.11 3534.54,1049.27 3582.54,1049.27 3630.54,1049.27 3678.54,1049.27 3726.43,1052.48 4237.31,1058.52 3907.31,1059.11 3432.94,1063.21 4077.77,1066.61 3770.97,1070.38 4101.44,1072.63 4168.65,1072.35 3272.64,1074.4 3361.13,1075.16 1570.18,1078.57 466.21,1078.73 701.64,1078.73 3947.4,1085.52 5414.01,1087.07 5464.01,1087.07 5514.01,1087.07 5614.01,1087.07 5714.01,1087.07 5864.01,1087.07 5964.01,1087.07 479.93,1092.45 687.92,1092.45 3470.14,1093.56 3985.41,1094.61 3807.39,1101.64 525.1,1108.49 545.1,1108.49 565.1,1108.49 605.1,1108.49 625.1,1108.49 645.1,1108.49 3306.58,1108.34 3394.97,1109.19 3515.37,1109.61 4009.03,1110 4103.52,1110 4166.51,1110 4229.5,1110 4261,1110 4449.97,1110 4481.47,1110 4512.96,1110 3563.34,1111.31 3611.34,1111.31 3659.34,1111.31 3707.34,1111.93 468.12,1116.11 1092.52,1125.76 3438.83,1128.71 3486.83,1128.83 3534.83,1128.83 3582.83,1128.83 3630.83,1128.83 3750.64,1132.63 3841.7,1135.21 3678.3,1135.92 5364.01,1137.07 5764.01,1137.07 5814.01,1137.07 5914.01,1137.07 6014.01,1137.07 1446.12,1141.47 4009.03,1141.5 4040.52,1141.5 4072.02,1141.5 4449.97,1141.5 4512.96,1141.5 3340.52,1142.28 1092.52,1145.76 3887.49,1149.61 3915.49,1148.97 1193.54,1150.61 3963.46,1150.65 3720.17,1159.39 3784.59,1166.57 3377.68,1172.67 1446.12,1172.97 4009.03,1172.99 4040.52,1172.99 4072.02,1172.99 4198,1172.99 2520.05,1177.8 2657.26,1177.8 497.24,1179.07 5364.01,1187.07 5464.01,1187.07 5564.01,1187.07 5664.01,1187.07 5814.01,1187.07 5914.01,1187.07 6014.01,1187.07 2181.22,1187.88 3422.89,1188.78 3470.85,1190.86 3518.85,1190.86 3566.85,1190.86 3614.85,1190.86 3754.84,1192.58 3662.61,1195.59 3822.47,1196.04 497.24,1199.07 4040.52,1204.49 4229.5,1204.49 497.24,1219.07 670.91,1221.28 690.91,1221.28 710.91,1221.28 755.91,1221.28 775.91,1221.28 795.91,1221.28 840.91,1221.28 860.91,1221.28 880.91,1221.28 925.91,1221.28 945.91,1221.28 965.91,1221.28 2146.22,1222.88 2216.22,1222.88 3791.83,1223.18 3700.1,1225.57 1186.77,1226.05 3954.57,1228.66 3839.49,1228.83 3887.49,1228.83 4040.52,1235.98 4072.02,1235.98 4355.48,1235.98 4512.96,1235.98 5414.01,1237.07 5514.01,1237.07 5614.01,1237.07 5714.01,1237.07 5864.01,1237.07 5964.01,1237.07 497.24,1239.07 1570.57,1244.46 1146.3,1245.73 1227.3,1245.73 2520.05,1248.85 2657.26,1248.85 3734.65,1258.89 4009.03,1267.48 4040.52,1267.48 3776.11,1283.08 5414.01,1287.07 5764.01,1287.07 5864.01,1287.07 5964.01,1287.07 3975.22,1288.19 3823.47,1290.86 3871.47,1290.86 3897.71,1290.72 3927.29,1290.86 3438.11,1297.68 3486.11,1297.68 3534.11,1297.68 3582.11,1297.68 3630.11,1297.68 3678.11,1297.68 3726.11,1297.68 2682.16,1298.23 2770.74,1298.23 1326.19,1300.48 3390.38,1302.81 3347.19,1323.74 3865,1323.77 1326.19,1325.48 1767.23,1325.6 4040.52,1330.47 4072.02,1330.47 4481.47,1330.47 4512.96,1330.47 5364.01,1337.07 5464.01,1337.07 5564.01,1337.07 5664.01,1337.07 5814.01,1337.07 5914.01,1337.07 6014.01,1337.07 3312.25,1356.65 3897.43,1359.16 3416.15,1360.27 3464.14,1359.72 3512.14,1359.72 3560.14,1359.72 3608.14,1359.72 3656.14,1359.72 3704.14,1359.72 3752.14,1359.72 3800.13,1360.8 4040.52,1361.97 4072.02,1361.97 2377.59,1363.19 302.52,1366.75 3373.52,1382.33 302.52,1386.43 3840.95,1386.05 5364.01,1387.07 5514.01,1387.07 5614.01,1387.07 5714.01,1387.07 5814.01,1387.07 5914.01,1387.07 6014.01,1387.07 3278.31,1390.59 4072.02,1393.46 4512.96,1393.46 3915.19,1403.75 1257.87,1406.12 1282.87,1406.12 1431.1,1406.12 1456.1,1406.12 2946.87,1411.88 3339.58,1416.27 3247.77,1423.01 4072.02,1424.96 3856.11,1431.59 1431.1,1431.71 1456.1,1431.71 3812.71,1434.47 5414.01,1437.07 5764.01,1437.07 5864.01,1437.07 5964.01,1437.07 3305.64,1450.21 3212.72,1455.79 4009.03,1456.46 4040.52,1456.46 4072.02,1456.46 3907.91,1457.21 3955.91,1457.21 1785.14,1458.93 1631.72,1461.9 1651.72,1461.9 3860.98,1467.31 2946.87,1482.93 5414.01,1487.07 5464.01,1487.07 5564.01,1487.07 5664.01,1487.07 5864.01,1487.07 5964.01,1487.07 4040.52,1487.95 4512.96,1487.95 3335.51,1488.96 3178.77,1489.73 3784.67,1489.8 3257.23,1497.82 1634.95,1501.9 3803.76,1504.09 497.24,1514.11 3375.61,1515.34 3783.01,1518.17 4040.52,1519.45 4072.02,1519.45 2865.78,1521.22 3144.83,1523.67 3233.03,1523.21 3285.38,1525.78 670.91,1531.91 690.91,1531.91 710.91,1531.91 755.91,1531.91 775.91,1531.91 795.91,1531.91 840.91,1531.91 860.91,1531.91 880.91,1531.91 925.91,1531.91 945.91,1531.91 965.91,1531.91 1014.02,1533.24 497.24,1534.11 1249.93,1534.83 1467.1,1534.83 5364.01,1537.07 5514.01,1537.07 5614.01,1537.07 5714.01,1537.07 5814.01,1537.07 5914.01,1537.07 6014.01,1537.07 1535.1,1539.51 263.22,1546.25 3963.56,1550.19 4009.03,1550.94 4040.52,1550.94 4072.02,1550.94 4198,1550.94 4261,1550.94 497.24,1554.11 3110.89,1557.62 3199.09,1557.15 3321.18,1557.76 3856.24,1564.91 3917.72,1566.95 3821.18,1568.45 2370.59,1570.44 1674.32,1570.9 497.24,1574.11 3365.42,1576.36 3775.18,1582.15 4009.03,1582.44 4040.52,1582.44 4072.02,1582.44 4103.52,1582.44 4135.01,1582.44 4166.51,1582.44 4198,1582.44 4229.5,1582.44 4261,1582.44 4449.97,1582.44 4481.47,1582.44 4512.96,1582.44 5364.01,1587.07 5764.01,1587.07 5814.01,1587.07 5914.01,1587.07 6014.01,1587.07 3076.95,1591.56 3165.15,1591.1 3847.25,1612.06 432.77,1613.27 571.88,1613.27 3912.67,1614.68 4009.03,1613.94 4103.52,1613.94 4166.51,1613.94 4229.5,1613.94 4261,1613.94 4449.97,1613.94 4481.47,1613.94 4512.96,1613.94 3043.01,1625.5 3131.2,1625.04 2370.59,1629.49 432.77,1633.27 571.88,1633.27 1600.94,1635.48 5414.01,1637.07 5464.01,1637.07 5564.01,1637.07 5664.01,1637.07 5864.01,1637.07 5964.01,1637.07 3947.33,1638.44 3810.91,1643.42 1348.36,1644.63 3235.13,1647.68 3283.13,1647.68 3331.13,1647.68 3379.13,1647.68 3427.13,1647.68 3475.13,1647.68 3523.13,1647.68 3571.13,1647.68 3619.13,1647.68 4164.79,1647.19 4230.35,1647.26 3667.12,1647.96 3715.12,1647.96 3763.12,1647.96 3194.14,1649.25 4081.24,1652.14 432.77,1653.27 571.88,1653.27 3009.07,1659.44 3097.26,1658.98 727.63,1660.2 747.63,1660.2 767.63,1660.2 797.63,1660.2 817.63,1660.2 837.63,1660.2 889.36,1660.2 909.36,1660.2 929.36,1660.2 5012.01,1664.13 3907.26,1664.86 1600.93,1666.99 3149.83,1667.71 2370.59,1668.86 2146.22,1672.88 2216.22,1672.88 1198.12,1674.63 4088.66,1676.01 4175.39,1677.7 4044.53,1683.06 5414.01,1687.07 5514.01,1687.07 5614.01,1687.07 5714.01,1687.07 5864.01,1687.07 5964.01,1687.07 4255.77,1687.97 2975.13,1693.38 3063.32,1692.92 4150.88,1693.13 1198.12,1694.63 3997.99,1694.8 3873.36,1698.85 3114.82,1700.55 3810.95,1707.28 2181.22,1707.88 3221.25,1708.49 3667,1709.44 3715,1709.44 3763,1709.44 1719.79,1710.64 3286.69,1709.72 3334.69,1709.72 3382.69,1709.72 3430.69,1709.72 3478.69,1709.72 3526.69,1709.72 3574.69,1709.72 3622.69,1709.72 4054.99,1710.23 3953.3,1712.33 4200.03,1718.9 1341.59,1720.06 4289.07,1722.55 3176.71,1726.4 2941.19,1727.32 3029.38,1726.86 4121.7,1731.24 5012.01,1731.23 3839.42,1732.79 3081.27,1734.87 389.38,1737.64 5364.01,1737.07 5764.01,1737.07 5814.01,1737.07 5914.01,1737.07 6014.01,1737.07 1301.11,1739.75 1382.11,1739.75 3919.36,1746.27 4018.64,1752.92 4233.43,1753.36 4325.5,1754.04 3142.77,1760.34 5012.01,1760.03 2907.25,1761.26 2995.44,1760.8 3805.48,1766.73 3972.67,1766.73 4091.02,1768.15 4369.37,1773.53 3055.92,1775.63 3885.42,1780.21 5364.01,1787.07 5464.01,1787.07 5564.01,1787.07 5664.01,1787.07 5814.01,1787.07 5914.01,1787.07 6014.01,1787.07 2760.9,1793.43 1481,1794.49 2873.3,1795.2 2961.5,1794.74 3113.05,1798.03 3937.15,1799.02 3771.54,1800.67 1888.35,1802.71 1931.66,1802.71 389.38,1805.64 4403.81,1806.96 4091.02,1809.44 4028.98,1812.52 4242,1812.52 727.63,1813.27 747.63,1813.27 767.63,1813.27 889.36,1813.27 909.36,1813.27 929.36,1813.27 3851.48,1814.15 4313.82,1814.96 4008.38,1817.13 1481,1819.49 3046.58,1822.72 2927.56,1828.68 2839.36,1829.14 5012.01,1829.14 1248.96,1831.57 3903.21,1832.96 3737.6,1834.61 4131.59,1835.09 5414.01,1837.07 5514.01,1837.07 5614.01,1837.07 5714.01,1837.07 5864.01,1837.07 5964.01,1837.07 389.38,1839.64 4437.4,1841.25 1639.27,1842.24 2535.13,1842.81 2661.86,1842.81 4352.5,1843.39 2482.67,1846.11 3108.53,1845.82 3817.54,1848.09 3973.64,1850.26 1624.27,1857.24 4045.24,1857.69 4258.25,1857.69 2893.62,1862.62 2805.42,1863.09 3703.66,1868.55 466.21,1870.26 701.64,1870.26 3046.49,1870.72 3874.63,1871.52 4386.44,1877.33 1227.12,1878.1 4152.69,1878.2 4365.71,1878.2 3783.6,1882.03 4462.89,1881.93 479.93,1883.98 687.92,1883.98 3939.77,1884.26 5414.01,1887.07 5764.01,1887.07 5864.01,1887.07 5964.01,1887.07 3108.53,1893.82 2859.68,1896.57 4068.69,1899.57 4281.71,1899.57 525.1,1900.02 545.1,1900.02 565.1,1900.02 605.1,1900.02 625.1,1900.02 645.1,1900.02 2775.99,1901 3669.72,1902.49 468.12,1907.64 2535.13,1913.86 2661.86,1913.86 3749.66,1915.97 3861.55,1917.71 3046.49,1918.72 4409.77,1919.28 4129.28,1920.1 4342.29,1920.1 3922.33,1928.99 4472.34,1928.99 2828.78,1933.3 3635.78,1936.44 5364.01,1937.07 5464.01,1937.07 5564.01,1937.07 5664.01,1937.07 5814.01,1937.07 5914.01,1937.07 6014.01,1937.07 1932.53,1938.09 1962.28,1938.09 3108.53,1941.82 2761.8,1946.86 3715.72,1949.92 4096.15,1952.66 4309.17,1952.66 4143.52,1960.46 4356.53,1960.46 3860.49,1965.7 3046.49,1966.72 4410.49,1967.27 3601.83,1970.38 3922.53,1976.99 4472.53,1976.99 2822.53,1980.9 3681.78,1983.86 5364.01,1987.07 5514.01,1987.07 5614.01,1987.07 5714.01,1987.07 5814.01,1987.07 5914.01,1987.07 6014.01,1987.07 3108.53,1989.82 4067.31,1991.03 4280.33,1991.03 2760.49,1994.84 183.07,1998.14 320.21,1999.98 345.21,1999.98 3567.89,2004.32 4150.82,2007.9 4363.84,2007.9 3860.49,2013.7 3046.49,2014.72 4410.49,2015.27 1603.83,2015.78 934.41,2017.12 3647.83,2017.8 3922.53,2024.99 4472.53,2024.99 2822.53,2028.9 4078.98,2037.59 4292,2037.59 5414.01,2037.07 5764.01,2037.07 5864.01,2037.07 5964.01,2037.07 3108.53,2037.82 2760.49,2042.84 3613.89,2051.74 4140.95,2054.87 4353.96,2054.87 3027.09,2058.62 3512.76,2060.58 3860.49,2061.7 4410.49,2063.27 422.59,2064.43 387.33,2069.42 4084.45,2072.6 4135.55,2072.6 4297.46,2072.6 4348.57,2072.6 3922.53,2072.99 4472.53,2072.99 2981.55,2073.78 2822.53,2076.9 3102.56,2085.45 5414.01,2087.07 5464.01,2087.07 5564.01,2087.07 5664.01,2087.07 5764.01,2087.07 5864.01,2087.07 5964.01,2087.07 2760.49,2090.84 3546.7,2094.53 4354.15,2097.41 4078.22,2098.51 4160.28,2101.58 4272.74,2101.58 717.87,2102.12 1745.94,2101.83 3860.49,2109.7 4410.49,2111.27 2955.57,2114.15 3066.74,2117.4 3922.53,2120.99 4472.53,2120.99 3019.02,2122.6 1322.75,2124.58 2822.53,2124.9 1156.57,2127.4 1915.91,2131.95 1947.4,2131.95 5364.01,2137.07 5514.01,2137.07 5614.01,2137.07 5714.01,2137.07 5814.01,2137.07 5914.01,2137.07 6014.01,2137.07 2760.49,2138.84 720.98,2143.34 4354.03,2144.16 255.25,2145.62 280.25,2145.62 4078.98,2145.61 4292,2153.21 3860.49,2157.7 4410.49,2159.27 2953.58,2162.1 720.98,2163.34 3922.53,2168.99 4185.68,2168.83 4246.7,2169.09 4472.53,2168.99 3015.62,2170.47 2822.53,2172.9 720.98,2183.34 2760.49,2186.84 5364.01,2187.07 5514.01,2187.07 5614.01,2187.07 5714.01,2187.07 5814.01,2187.07 5914.01,2187.07 6014.01,2187.07 4347.17,2191.67 454.97,2194.67 4214.86,2205.01 3860.49,2205.7 1136.57,2206.77 1227.12,2206.77 4410.49,2207.27 2953.58,2210.1 3922.53,2216.99 4472.53,2216.99 3015.62,2218.47 2822.53,2220.9 4124.77,2222.24 4309.78,2221.76 2760.49,2234.84 3990.52,2235.1 5414.01,2237.07 5464.01,2237.07 5664.01,2237.07 5764.01,2237.07 5864.01,2237.07 5964.01,2237.07 3058.65,2239.74 747.88,2242.08 4216.51,2250.21 4272.72,2252.27 3860.49,2253.7 4160.3,2254.52 4410.49,2255.27 2959.98,2257.68 3922.53,2264.99 3990.52,2265.1 4472.53,2264.99 3098.65,2266.27 2822.53,2268.9 2760.49,2282.84 4135.8,2285.65 4297.22,2285.65 5414.01,2287.07 5464.01,2287.07 5664.01,2287.07 5764.01,2287.07 5864.01,2287.07 2992.9,2292.61 4184.51,2293.24 4216.51,2293.24 4248.51,2293.24 3040.26,2300.42 3860.49,2301.7 4410.49,2303.27 4135.8,2311.24 4200.51,2311.24 4232.51,2311.24 4297.22,2311.24 3108.53,2313.24 3922.53,2312.99 4472.53,2312.99 2822.53,2316.9 4184.51,2329.24 4216.51,2329.24 4248.51,2329.24 2760.49,2330.84 4045.59,2332.86 4135.8,2336.83 4297.22,2336.83 5514.01,2337.07 5614.01,2337.07 5714.01,2337.07 5814.01,2337.07 5914.01,2337.07 6014.01,2337.07 925.57,2340.51 3048.72,2347.67 3860.49,2349.7 4410.49,2351.27 3124.28,2358.59 3922.53,2360.99 4472.53,2360.99 3171.96,2364.12 3219.96,2364.12 2822.53,2364.9 3267.88,2366.92 3990.52,2370.14 4090.52,2370.14 4190.92,2372.26 4242.1,2372.26 2760.49,2378.84 3312.4,2384.84 3069.34,2391.02 255.25,2397.59 280.25,2397.59 895.04,2396.73 3860.49,2397.7 453.59,2399.56 487.59,2399.56 4410.49,2399.27 3990.52,2400.14 4090.52,2400.14 1136.57,2406.77 1227.12,2406.77 4185.49,2407.13 3922.53,2408.99 4472.53,2408.99 2822.53,2412.9 4128.19,2414.12 4265.97,2414.12 4313.97,2414.12 4361.97,2414.12 3347.37,2417.73 3108.18,2419.23 3155.67,2426.15 3203.67,2426.15 3251.67,2426.68 2760.49,2426.84 527.59,2429.25 547.59,2429.25 567.59,2429.25 3861.87,2433.08 4491.79,2445.14 4017.18,2446.61 3293.97,2449.37 2822.53,2460.9 3367.89,2461.12 3922.53,2460.9 2760.49,2474.84 4056.05,2474.78 4243.35,2475.24 4104.03,2476.16 4152.03,2476.16 4200.03,2476.16 4291.34,2476.16 4339.34,2476.16 4387.34,2476.16 4471.15,2478.31 1642.36,2480.66 3860.49,2481.05 3310.49,2494.43 4410.5,2508.44 2822.53,2508.9 3372.53,2508.9 3922.53,2508.9 4472.53,2508.9 3859.1,2519.04 2760.49,2522.84 776.93,2585.47 1160.19,2606.41 1203.5,2606.41
  other v4: 3977.32,617.67
HSPC-PRSNT-M2C-L: J1.Z1 R229.2 | length 5.3
  Top Layer w10: R229.2@5964.01,2331.75 v1(5964.01,2337.07)
ISENSE-DVDD: U5.7 U9.4 | length 1931.4
  L10 SIG w5: v1(1088.82,1572.61) 1088.82,1504.7 1144.72,1448.8 1176.93,1448.8 1226.02,1399.71 1226.02,1297.88 1410.69,1113.21 1504.78,1113.21 1689.62,928.37 2190.86,928.37 2228.28,890.95 2228.28,890.78 2283.89,835.18 2361.4,835.18 2408.11,881.89 2463.04,881.89 2471.99,890.84 2493.88,890.84 v1(2533.67,930.64)
  Bottom Layer w5: v1(2533.67,930.64) 2537.19,930.64 2542.19,925.64 U5.7@2573.67,925.64
ISENSE-VDD18: U5.5 U15.4 | length 1166.5
  Top Layer w18: v1(1937,275.81) U15.4@1977,275.81
  L10 SIG w5: v1(1937,275.81) 1943.04,275.81 2032.61,365.37 2032.61,476.93 2063.1,507.43 2243.35,507.43 2375.72,639.8 2500.85,639.8 2583.72,722.67 2583.72,731.38 2606.09,753.76 2606.09,831.96 2577.8,860.26 2577.8,881.85 2570.5,889.14 v1(2553.67,889.14)
  Bottom Layer w5: v1(2553.67,889.14) 2556.86,889.14 2561.86,894.14 U5.5@2573.67,894.14
ISENSE-VDDCLK08: U5.8 U30.4 | length 892.6
  L10 SIG w5: v1(1863.97,1064.83) 1877.99,1050.81 2184.27,1050.81 2194.27,1040.81 2207.14,1040.81 2224.51,1023.44 2367.91,1023.44 2389.69,1045.23 2582.76,1045.23 2600.52,1027.47 2600.52,1016.39 2553.67,969.54 v1(2553.67,946.38)
  Bottom Layer w5: v1(2553.67,946.38) 2556.86,946.38 2561.86,941.38 U5.8@2573.67,941.38
ISENSE-VDDLx: U5.9 U26.4 | length 1318.2
  L10 SIG w5: v1(1863.97,694.83) 1864.84,694.83 1948.93,610.74 1948.93,481.83 1962.8,467.96 1994.67,467.96 2048.6,521.9 2048.6,540.05 2097.61,589.05 2254.04,589.05 2314.79,649.8 2496.7,649.8 2573.72,726.81 2573.72,819.73 2563.72,829.73 2563.72,840.36 2537.17,866.9 2537.17,903.82 2550.43,917.07 2573.47,917.07 2582.72,926.33 2582.72,973.83 v1(2582.3,974.26)
  Bottom Layer w5: v1@2587.3,971.07 2597.3,961.07 U5.9@2597.3,949.26
ISENSE-VEEAM18: U5.10 U20.1 | length 1670.9
  L10 SIG w5: v1(1288.79,1312.98) 1288.79,1278.3 1443.87,1123.21 1539.81,1123.21 1569.95,1093.07 1650.16,1093.07 1760.26,982.97 1966.34,982.97 1992.92,956.38 2176.99,956.38 2282.11,851.27 2357.86,851.27 2423.67,917.07 2435.62,917.07 2448.12,929.57 2488.12,929.57 2505.68,947.14 2518.91,947.14 2541.59,969.82 2541.59,989.82 v1(2575.21,1023.44)
  Bottom Layer w5: v1(2575.21,1023.44) 2611.94,986.71 2611.94,965.93 2613.04,964.83 U5.10@2613.04,949.26
ISENSE-VEEBM18: U5.3 U25.1 | length 2087.6
  Top Layer w5: v1(1443.6,1806.99) 1443.6,1773.51 1467.1,1750.01 1579.71,1750.01 1624.19,1794.49 1731.48,1794.49 1754.73,1771.24 1754.73,1719.95 1778.67,1696.01 1840.16,1696.01 1866.32,1669.85 1959.08,1669.85 2002.61,1626.32 2002.61,1539.51 1982.26,1519.16 1982.26,1094.04 2012.1,1064.2 2305.52,1064.2 2306.16,1064.83 2430.62,1064.83 2482.96,1012.49 2522.46,1012.49 2553.96,980.99 2553.96,979.26 2570.17,963.05 2570.17,865.05 2585.46,849.77 2599.13,849.77 2600.17,850.81 2612.58,850.81 v1(2613.04,851.27)
  Bottom Layer w5: v1(2613.04,851.27) U5.3@2613.04,886.27
ISENSE_CLOCKING: U5.4 U34.4 | length 1442.7
  Top Layer w5: v1(1794.59,1750.01) 1794.59,1740.17 1805.78,1728.98 1927.74,1728.98 2012.1,1644.63 2012.1,1630 2012.61,1629.49 2012.61,1521.98 2120.64,1413.94 2315.03,1413.94 2357.27,1371.71 2357.27,1266.25 2496.14,1127.38 2519.92,1127.38 2600.96,1046.34 2600.96,947.44 2592.3,938.78 v1(2592.3,866.27)
  Bottom Layer w5: v1(2592.3,866.27) 2592.3,869.46 2597.3,874.46 U5.4@2597.3,886.27
LMK_C\S\: PP35.1 R138.2 U48.10 U54.18 | length 2790.3
  L10 SIG w5: v1(1593.74,2324.88) 1533.85,2324.88 1501.62,2292.65 1501.62,2222.1 1508.79,2214.92 1508.79,2202.91 1501.62,2195.73 1501.62,2154.43 1577.39,2078.65 1577.39,1982.34 1615.89,1943.85 1615.89,1905.47 1687.4,1833.96 1804.17,1833.96 1818.64,1848.43 1818.64,1954.39 2006.51,2142.26 2125.78,2142.26 2433.17,1834.88 2433.17,1815.14 2512.79,1735.52 2546.66,1735.52 2547.31,1734.87 2673.16,1734.87 2724.29,1683.74 2724.29,1458.03 2859.68,1322.64 PP35.1@2859.68,1267.5
  Bottom Layer w5: v1(1593.74,2324.88) 1597.26,2324.88 1602.26,2329.88 U48.10@1623.74,2329.88 ; U54.18@2746.14,1372.6 2746.14,1281.06 2754.49,1272.71 R138.2@2813.86,1272.71 2854.47,1272.71 PP35.1@2859.68,1267.5
LMK_DCLKOUT4_N: C167.2 R162.2 U54.25 | length 68.2
  Bottom Layer w6.3: U54.25@2608.34,1372.6 2608.34,1369.03 ccw(c2616.35,1369.03) 2610.69,1363.37 cw(c2605.02,1357.7) 2613.03,1357.7 2613.03,1343.81 cw(c2609.73,1343.81) 2612.07,1341.47 ccw(c2614.4,1339.13) 2611.1,1339.13 2611.1,1337.98 cw(c2605.72,1337.98) R162.2@2609.53,1334.18
  Bottom Layer w12.1: C167.2@2605.66,1307.6 2605.66,1324.84 cw(c2618.87,1324.84) R162.2@2609.52,1334.18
